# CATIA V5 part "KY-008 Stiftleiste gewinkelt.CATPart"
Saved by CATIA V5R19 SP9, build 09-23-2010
Part number: Stiftleiste gewinkelt
Bounding box of the stored display mesh (mm): x -1.27 to 7.62, y -4.128 to 3.175, z -1.27 to 6.35
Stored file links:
  D:\Temporäre Sachen\Lasermodul KY-008 with mounting for adjustment\KY-008 Stiftleiste gewinkelt.CATPart
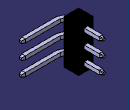
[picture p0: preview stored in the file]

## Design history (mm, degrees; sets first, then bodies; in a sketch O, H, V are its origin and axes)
Parameters
  inch2mm = 2.54 mm
AxisSystem1: origin (0, 0, 0), X (1, 0, 0), Y (0, 1, 0), Z (0, 0, 1)
AxisSystem2: origin (1.27, -3.81, 0), X (1, 0, 0), Y (0, 1, 0), Z (0, 0, 1)
Body1 (main body)
  Sketch1 on xy-plane, origin (0, 0, 0), H (1, 0, 0), V (0, 1, 0)
    point P1 (0, 3.175)
    line L1 (0, 3.175) -> (0, -2.81)
    arc A1 centre (1, -2.81) radius 1 from (0, -2.81) to (1, -3.81) ccw
    line L2 (1, -3.81) -> (7.62, -3.81)
    point P5 (7.62, -3.81)
    distance P1 H = 3.175 {= 1.25*inch2mm}
    distance H L2 = 3.81 {= 1.5*inch2mm}
    radius A1 = 1
    distance P5 L1 = 7.62 {= 3*inch2mm}
    coincidence: P1 V
    vertical: L1 V
    tangency: A1 L1, L2 A1
  Pad1: profile Sketch1, direction (0, 0, 1), length 0.3175 {= .25*inch2mm /2}, mirrored extent, thin wall 0.3175 {= .25*inch2mm /2}, second thickness 0.3175 {= .25*inch2mm /2}
  Chamfer1: length 0.15, angle 75, on face of Pad1 (x2)
  Fillet1: radius 0.1, on edge [face of Chamfer1 | face of Chamfer1] (x4)
  Sketch2 on zx-plane, origin (0, 0, 0), H (-1, 0, 0), V (0, 0, 1)
    line L1 (1.27, 1.27) -> (1.27, -1.27)
    line L2 (1.27, -1.27) -> (-1.27, -1.27)
    line L3 (-1.27, -1.27) -> (-1.27, 1.27)
    line L4 (-1.27, 1.27) -> (1.27, 1.27)
    distance L2 L4 = 2.54 {= Sketch2.distance(L1 L3)}
    distance L1 L3 = 2.54 {= 1*inch2mm}
    vertical: L1 V, L3 V
    horizontal: L2 H, L4 H
    equidistance: L1 L3 O, L2 L4 O
  Pad2: profile Sketch2, direction (0, -1, 0), length 2.54 {= 1*inch2mm}
  RectPattern1: of the body so far, direction 1 instances 3, spacing 2.54 {= 1*inch2mm}, along zx-plane
Relations
  AxisSystem2.OriginY = -1.5*inch2mm
  AxisSystem2.OriginX = .5*inch2mm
